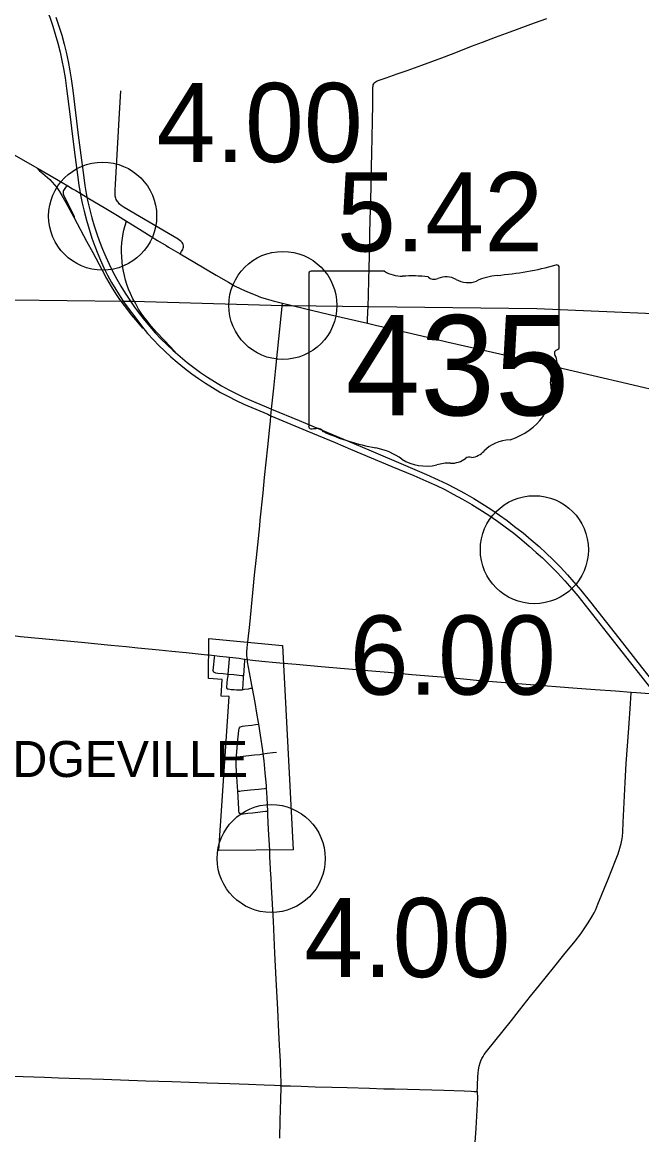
# Model space of a CAD drawing. Extents: x 1597222 to 1925846, y 496284 to 911751.
# Drawn here: x 1658757 to 1667359, y 576766 to 592215 of the extents above; entities that cross this region are included whole.
import ezdxf

# ---------------------------------------------------------------- set-up
doc = ezdxf.new("R2010")
doc.units = 0
for name, color, linetype in [('Default', 7, 'Continuous'), ('GM_X_City_Street', 7, 'Continuous'), ('GM_X_Corporation', 7, 'Continuous'), ('GM_X_Corporation_Text', 7, 'Continuous'), ('GM_X_County_Road', 7, 'Continuous'), ('GM_X_Interchange_Ramps', 7, 'Continuous'), ('GM_X_State_Route', 7, 'Continuous'), ('GM_X_State_Shield', 7, 'Continuous'), ('GM_X_Township', 7, 'Continuous'), ('GM_X_Township_Road', 7, 'Continuous'), ('GM_X_US_Route', 7, 'Continuous')]:
    doc.layers.add(name, color=color, linetype=linetype)

msp = doc.modelspace()

# ---------------------------------------------------------------- linework, layer by layer
at = {"layer": 'Default'}
for centre in [(1659873, 589523), (1659873, 589523), (1662376, 588283), (1662376, 588283), (1665868, 584891), (1665868, 584891), (1662214, 580602), (1662214, 580602)]:
    msp.add_circle(centre, 750, dxfattribs=at)
at = {"layer": 'GM_X_City_Street'}
for points in [[(1661351, 583429), (1661427, 583421)], [(1661427, 583421), (1661424, 583393), (1661414, 583296), (1661405, 583215), (1661407, 583207), (1661409, 583200), (1661414, 583193), (1661420, 583189), (1661430, 583185), (1661441, 583182), (1661475, 583177), (1661548, 583171), (1661616, 583164)], [(1661427, 583421), (1661496, 583414), (1661592, 583405), (1661635, 583399)], [(1661616, 583164), (1661626, 583271), (1661634, 583373), (1661635, 583399)], [(1661635, 583399), (1661769, 583383), (1661817, 583376), (1661848, 583370)], [(1661832, 583144), (1661847, 583350), (1661848, 583370)], [(1661848, 583370), (1661883, 583364)], [(1661883, 583364), (1661953, 583356), (1662084, 583342), (1662281, 583325), (1662385, 583316)], [(1661820, 582944), (1661804, 582942), (1661794, 582940), (1661780, 582939), (1661760, 582939), (1661732, 582941), (1661698, 582944), (1661657, 582947), (1661614, 582952), (1661610, 582954), (1661607, 582956), (1661604, 582959), (1661602, 582962), (1661600, 582967), (1661599, 582970), (1661598, 582975), (1661598, 582978), (1661604, 583040), (1661609, 583092), (1661614, 583141), (1661616, 583164)], [(1661616, 583164), (1661694, 583156), (1661807, 583146), (1661832, 583144)], [(1661820, 582944), (1661820, 582960), (1661821, 582970), (1661824, 583016), (1661831, 583124), (1661832, 583144)], [(1661952, 582965), (1661926, 582961), (1661893, 582956), (1661845, 582948), (1661820, 582944)], [(1661732, 582013), (1661733, 582027), (1661752, 582256), (1661754, 582288), (1661764, 582386), (1661768, 582402), (1661774, 582417), (1661785, 582429), (1661800, 582436), (1661816, 582439), (1661849, 582443), (1661946, 582456), (1661995, 582463), (1662041, 582470)], [(1661750, 581536), (1661740, 581667), (1661731, 581814), (1661726, 581896), (1661727, 581945), (1661731, 581994), (1661732, 582013)], [(1661732, 582013), (1661783, 582018), (1661984, 582041), (1662056, 582049), (1662102, 582056)], [(1662102, 582056), (1662156, 582064), (1662237, 582075), (1662286, 582081)], [(1661750, 581536), (1661780, 581539), (1661796, 581540), (1661925, 581555), (1662039, 581567), (1662119, 581575), (1662149, 581579)], [(1662165, 581257), (1662133, 581253), (1661954, 581233), (1661889, 581226), (1661824, 581218), (1661807, 581217), (1661791, 581220), (1661777, 581228), (1661769, 581242), (1661765, 581258), (1661763, 581291), (1661750, 581536)]]:
    msp.add_lwpolyline(points, dxfattribs=at)
at = {"layer": 'GM_X_Corporation'}
msp.add_lwpolyline([(1661348, 583658), (1662369, 583561), (1662517, 580722), (1661488, 580713), (1661631, 582852), (1661519, 582859), (1661531, 583087), (1661343, 583102)], close=True, dxfattribs=at)
at = {"layer": 'GM_X_County_Road'}
for points in [[(1656846, 583945), (1656933, 583938), (1657439, 583898), (1657717, 583874), (1657814, 583863), (1657895, 583851), (1657992, 583831), (1658264, 583770), (1658472, 583725), (1658552, 583710), (1658633, 583697), (1658731, 583685), (1659579, 583605), (1659987, 583565), (1660199, 583545), (1660362, 583530), (1660656, 583500), (1660835, 583483), (1661031, 583462), (1661324, 583432), (1661351, 583429)], [(1662385, 583316), (1662559, 583301)], [(1662559, 583301), (1662908, 583271), (1663610, 583209), (1663839, 583189), (1664165, 583159), (1664459, 583134), (1664639, 583119), (1664739, 583110), (1664883, 583097), (1665112, 583076), (1665406, 583051), (1665815, 583018), (1666403, 582973), (1666714, 582949), (1666992, 582929), (1667214, 582912)], [(1667214, 582912), (1667286, 582907), (1667465, 582892)], [(1658375, 577587), (1658769, 577573), (1659064, 577564), (1659261, 577557), (1659556, 577547), (1659884, 577536), (1660474, 577516), (1660835, 577504), (1661327, 577488), (1661638, 577479), (1661900, 577469), (1662114, 577461), (1662261, 577453), (1662338, 577448), (1662351, 577447)], [(1662351, 577447), (1662482, 577444), (1662629, 577439), (1662826, 577433), (1663055, 577428), (1663268, 577422), (1663580, 577413), (1663777, 577406), (1663924, 577403), (1664104, 577399), (1664612, 577384), (1664892, 577374), (1664990, 577371), (1665034, 577368), (1665073, 577366)], [(1665073, 577366), (1665075, 577330), (1665077, 577306), (1665079, 577273), (1665054, 576858), (1665019, 576335)]]:
    msp.add_lwpolyline(points, dxfattribs=at)
at = {"layer": 'GM_X_Interchange_Ramps'}
for points in [[(1658970, 590188), (1658980, 590172), (1658987, 590162), (1658996, 590150), (1659041, 590115), (1659077, 590086), (1659139, 590030), (1659174, 589995), (1659207, 589958), (1659237, 589920), (1659274, 589866), (1659309, 589810), (1659364, 589710), (1659472, 589508), (1659476, 589501), (1659649, 589176), (1659735, 589018), (1659865, 588772), (1659928, 588657), (1659994, 588544), (1660054, 588447), (1660109, 588366), (1660126, 588343), (1660140, 588325), (1660203, 588239), (1660271, 588150), (1660358, 588049), (1660400, 588000), (1660417, 587983), (1660435, 587966), (1660447, 587956)], [(1659392, 589942), (1659373, 589928), (1659359, 589919), (1659347, 589908), (1659337, 589895), (1659329, 589881), (1659325, 589865), (1659324, 589849), (1659327, 589833), (1659332, 589817), (1659345, 589788), (1659463, 589548), (1659476, 589518), (1659477, 589510), (1659476, 589501)], [(1660883, 587631), (1660882, 587634), (1660879, 587638), (1660857, 587663), (1660820, 587702), (1660623, 587910), (1660547, 587996), (1660485, 588072), (1660445, 588124), (1660408, 588177), (1660373, 588233), (1660333, 588304), (1660314, 588338), (1660294, 588376), (1660259, 588450), (1660234, 588510), (1660211, 588572), (1660192, 588634), (1660175, 588697), (1660161, 588761), (1660151, 588826), (1660143, 588890), (1660138, 588956), (1660136, 589021), (1660137, 589086), (1660141, 589152), (1660148, 589217), (1660159, 589281), (1660169, 589329), (1660181, 589377), (1660186, 589392), (1660206, 589452)]]:
    msp.add_lwpolyline(points, dxfattribs=at)
at = {"layer": 'GM_X_State_Route'}
for points in [[(1658299, 590586), (1658313, 590577), (1658500, 590462), (1658646, 590376), (1658832, 590268), (1658970, 590188)], [(1658970, 590188), (1659231, 590037), (1659392, 589942), (1659457, 589903), (1659501, 589877)], [(1659501, 589877), (1659563, 589841), (1659656, 589785), (1659683, 589769), (1659896, 589643), (1660078, 589531), (1660206, 589452)], [(1660206, 589452), (1660287, 589402), (1660421, 589317), (1660547, 589239), (1660635, 589186), (1660755, 589113)], [(1660755, 589113), (1660786, 589094), (1660950, 588998), (1661153, 588878), (1661449, 588703), (1661619, 588604), (1661706, 588557), (1661794, 588513), (1661883, 588473), (1661989, 588428), (1662066, 588399), (1662144, 588374), (1662239, 588346), (1662370, 588315)], [(1662203, 586676), (1662211, 586752), (1662220, 586842), (1662249, 587133), (1662277, 587410), (1662300, 587639), (1662370, 588315)], [(1662370, 588315), (1662657, 588245), (1663024, 588158), (1663551, 588037), (1663664, 588011), (1663967, 587939), (1664382, 587843), (1664654, 587779), (1665532, 587576), (1666267, 587405), (1666682, 587309), (1667162, 587198), (1667417, 587138), (1667705, 587072), (1668168, 586964), (1668393, 586915)], [(1662062, 585299), (1662100, 585681), (1662122, 585893), (1662165, 586317), (1662194, 586594), (1662203, 586676)], [(1661890, 583607), (1661915, 583852), (1661960, 584293), (1661984, 584538), (1662010, 584783), (1662055, 585223), (1662062, 585299)], [(1662167, 581215), (1662165, 581257), (1662156, 581450), (1662149, 581579), (1662147, 581614), (1662131, 581793), (1662114, 581957), (1662102, 582056), (1662097, 582103), (1662065, 582314), (1662041, 582470), (1662038, 582493), (1662016, 582622), (1661989, 582767), (1661952, 582965), (1661943, 583009), (1661913, 583187), (1661887, 583333), (1661883, 583364), (1661880, 583382), (1661877, 583432), (1661877, 583465), (1661881, 583531), (1661890, 583607)], [(1662193, 580718), (1662177, 581007), (1662167, 581204), (1662167, 581215)], [(1662197, 580629), (1662193, 580718)], [(1662335, 576718), (1662339, 576964), (1662347, 577259), (1662351, 577423), (1662351, 577447), (1662352, 577488), (1662349, 577619), (1662342, 577783), (1662330, 578012), (1662321, 578192), (1662306, 578504), (1662284, 578929), (1662265, 579290), (1662244, 579732), (1662220, 580207), (1662213, 580338), (1662211, 580371), (1662197, 580629)]]:
    msp.add_lwpolyline(points, dxfattribs=at)
at = {"layer": 'GM_X_State_Shield'}
for p, q in [((1666214, 587703), (1666214, 588809)), ((1662734, 588720), (1662734, 586607)), ((1663787, 588757), (1662768, 588757)), ((1666214, 587704), (1666214, 587703))]:
    msp.add_line(p, q, dxfattribs=at)
for centre, major_axis, start_param, end_param in [((1664974, 591638), (3691, 0), 4.814394, 5.042369), ((1666176, 588814), (38.7, 0), 6.141152, 7.989035), ((1662774, 588725), (40.3, 0), 1.712693, 3.28349), ((1664030, 589002), (391, 0), 4.042523, 4.731795), ((1664160, 587570), (1404, 0), 1.404758, 1.657858), ((1664478, 588736), (113, 0), 3.836095, 5.185415), ((1664644, 588491), (235, 0), 0.950623, 2.079405), ((1664947, 588826), (282, 0), 4.081561, 5.145723), ((1665445, 588111), (743, 0), 1.699011, 2.107814), ((1666173, 587699), (41.5, 0), 5.05454, 6.418171), ((1666205, 587622), (60, 0), 1.883978, 3.671073), ((1665824, 587483), (360, 0), 5.934695, 6.695948), ((1666353, 587241), (262, 0), 2.387724, 3.262537), ((1665181, 587100), (923, 0), 5.101752, 6.440018), ((1662774, 586602), (40.7, 0), 3.00124, 4.508301), ((1662780, 586819), (310, 0), 4.665946, 4.897461), ((1662844, 586485), (112, 0), 0.519207, 1.627899), ((1664257, 588384), (2665, 0), 4.195997, 4.488961), ((1663462, 585658), (834, 0), 0.823519, 1.323587), ((1665570, 586014), (506, 0), 1.647645, 2.488434), ((1664364, 586475), (529, 0), 4.026481, 4.996735), ((1664709, 586316), (282, 0), 4.691044, 5.507374), ((1664964, 586112), (79.4, 0), 1.147584, 2.315152), ((1664930, 586402), (298, 0), 4.937069, 5.64225), ((1664670, 585744), (435, 0), 1.495662, 1.94098)]:
    msp.add_ellipse(centre, major_axis=major_axis, ratio=0.8, start_param=start_param, end_param=end_param, dxfattribs=at)
at = {"layer": 'GM_X_Township'}
msp.add_lwpolyline([(1640772, 591419), (1641501, 591232), (1645959, 590087), (1646099, 590051), (1651332, 588679), (1652031, 588630), (1654972, 588478), (1658610, 588362), (1660153, 588344), (1660296, 588340), (1662371, 588281), (1662472, 588280), (1663570, 588267), (1665903, 588241), (1668490, 588131), (1673343, 587846), (1673034, 583935), (1673000, 583850), (1672955, 583266), (1672719, 580558), (1678923, 579915)], dxfattribs=at)
at = {"layer": 'GM_X_Township_Road'}
for points in [[(1663558, 588266), (1663564, 588427), (1663569, 588640), (1663578, 588967), (1663585, 589279), (1663590, 589476), (1663597, 589722), (1663602, 589968), (1663607, 590214), (1663611, 590394), (1663616, 590623), (1663619, 590837), (1663623, 591083), (1663624, 591279), (1663626, 591312), (1663628, 591329), (1663631, 591345), (1663637, 591360), (1663645, 591374), (1663656, 591385), (1663669, 591394), (1663683, 591402), (1663699, 591408), (1663808, 591445), (1663963, 591499), (1664102, 591547), (1664303, 591619), (1664581, 591719), (1664719, 591772), (1664871, 591833), (1664993, 591882), (1665146, 591940), (1665330, 592009), (1665530, 592083), (1665869, 592206), (1666039, 592267)], [(1660950, 588998), (1660969, 589031), (1660986, 589060), (1660992, 589076), (1660995, 589093), (1660995, 589110), (1660992, 589127), (1660985, 589144), (1660976, 589158), (1660965, 589170), (1660952, 589182), (1660924, 589201), (1660385, 589517), (1660173, 589643), (1660132, 589670), (1660108, 589691), (1660097, 589702), (1660087, 589715), (1660078, 589728), (1660070, 589742), (1660063, 589756), (1660057, 589771), (1660053, 589787), (1660049, 589802), (1660046, 589835), (1660046, 589883), (1660050, 589965), (1660102, 590868), (1660127, 591262)], [(1663551, 588037), (1663552, 588082), (1663556, 588190), (1663558, 588266)], [(1665073, 577366), (1665074, 577384), (1665076, 577407), (1665077, 577427), (1665078, 577457), (1665083, 577570), (1665086, 577620), (1665092, 577668), (1665101, 577717), (1665115, 577764), (1665126, 577795), (1665139, 577825), (1665155, 577853), (1665173, 577881), (1665202, 577921), (1665551, 578355), (1665663, 578496), (1665815, 578690), (1665938, 578843), (1666135, 579084), (1666279, 579263), (1666433, 579455), (1666513, 579558), (1666561, 579625), (1666615, 579707), (1666667, 579791), (1666698, 579848), (1666719, 579892), (1666751, 579968), (1666893, 580317), (1666995, 580576), (1667029, 580669), (1667055, 580747), (1667073, 580810), (1667079, 580836), (1667083, 580858), (1667087, 580882), (1667090, 580906), (1667095, 580972), (1667101, 581103), (1667128, 581659), (1667143, 581921), (1667178, 582411), (1667204, 582755), (1667214, 582905), (1667214, 582912)]]:
    msp.add_lwpolyline(points, dxfattribs=at)
at = {"layer": 'GM_X_US_Route'}
for points in [[(1658732, 593127), (1658799, 593014), (1658863, 592900), (1658917, 592798), (1658953, 592724), (1658995, 592635), (1659041, 592530), (1659091, 592408), (1659138, 592286), (1659181, 592161), (1659215, 592052), (1659250, 591925), (1659282, 591798), (1659307, 591686), (1659330, 591573), (1659351, 591443), (1659372, 591297), (1659417, 590939), (1659456, 590630), (1659493, 590337), (1659533, 590028), (1659545, 589947), (1659556, 589879)], [(1659225, 592286), (1659266, 592162), (1659305, 592037), (1659340, 591910), (1659367, 591799), (1659395, 591671), (1659419, 591542), (1659437, 591429), (1659459, 591266), (1659533, 590648), (1659569, 590371), (1659602, 590127), (1659627, 589948), (1659646, 589835), (1659656, 589785), (1659668, 589722), (1659694, 589610), (1659723, 589499), (1659755, 589389), (1659791, 589279), (1659830, 589171), (1659871, 589064), (1659916, 588958), (1659964, 588854), (1660015, 588750), (1660069, 588649), (1660126, 588549), (1660186, 588451), (1660249, 588355), (1660259, 588340), (1660315, 588261), (1660383, 588168), (1660454, 588078), (1660528, 587990), (1660604, 587904), (1660683, 587820), (1660764, 587739), (1660849, 587661), (1660883, 587631), (1660948, 587574), (1661049, 587491), (1661140, 587421), (1661233, 587353), (1661328, 587289), (1661426, 587227), (1661524, 587168), (1661625, 587112), (1661727, 587060), (1661831, 587010), (1661966, 586950), (1662177, 586860), (1662220, 586842), (1662601, 586683), (1663568, 586276), (1664143, 586034), (1664369, 585937), (1664533, 585863), (1664651, 585806), (1664768, 585746), (1664898, 585676), (1665025, 585602), (1665137, 585534), (1665261, 585454), (1665383, 585371), (1665489, 585294), (1665594, 585215), (1665710, 585124), (1665823, 585030), (1665934, 584933), (1666031, 584844), (1666125, 584753), (1666229, 584648), (1666330, 584540), (1666417, 584442), (1666512, 584330), (1666646, 584164), (1666869, 583881), (1667041, 583661), (1667354, 583260), (1667618, 582925)], [(1659556, 589879), (1659563, 589841), (1659567, 589818), (1659589, 589705), (1659615, 589594), (1659648, 589467), (1659685, 589341), (1659725, 589216), (1659764, 589108), (1659805, 589001), (1659843, 588911), (1659892, 588807), (1659943, 588704), (1659998, 588603), (1660056, 588504), (1660124, 588393), (1660159, 588342), (1660174, 588321), (1660389, 588031), (1660447, 587956), (1660463, 587934), (1660495, 587895), (1660573, 587811), (1660653, 587728), (1660735, 587648), (1660819, 587571), (1660906, 587496), (1661008, 587413), (1661112, 587333), (1661205, 587266), (1661300, 587203), (1661398, 587142), (1661511, 587076), (1661612, 587021), (1661729, 586962), (1661833, 586914), (1661999, 586843), (1662165, 586772), (1662191, 586761)], [(1662191, 586761), (1662211, 586752), (1662376, 586681), (1662709, 586543), (1663103, 586378), (1663314, 586289), (1663889, 586048), (1664192, 585921), (1664403, 585830), (1664508, 585783), (1664626, 585725), (1664742, 585664), (1664872, 585593), (1665000, 585519), (1665111, 585450), (1665235, 585369), (1665357, 585286), (1665463, 585209), (1665581, 585119), (1665696, 585026), (1665796, 584942), (1665895, 584854), (1665979, 584776), (1666085, 584673), (1666188, 584568), (1666289, 584459), (1666387, 584349), (1666471, 584248), (1666574, 584120), (1666877, 583732), (1667202, 583320), (1667516, 582920)]]:
    msp.add_lwpolyline(points, dxfattribs=at)

# ---------------------------------------------------------------- texts
at = {"layer": 'Default'}
for s, p in [('4.00', (1660623, 590273)), ('4.00', (1660623, 590273)), ('5.42', (1663126, 589033)), ('5.42', (1663126, 589033)), ('6.00', (1663303, 582878)), ('6.00', (1663303, 582878)), ('4.00', (1662673, 578955))]:
    msp.add_text(s, height=1100, dxfattribs=at).set_placement(p)
at = {"layer": 'GM_X_Corporation_Text'}
msp.add_text('MILLEDGEVILLE', height=500, rotation=0, dxfattribs=at).set_placement((1656690, 581734))
at = {"layer": 'GM_X_State_Shield'}
msp.add_text('435', height=1392.2, dxfattribs=at).set_placement((1663248, 586756))

doc.saveas('drawing.dxf')
